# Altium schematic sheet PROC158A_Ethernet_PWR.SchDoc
size 431 x 279 mm; Date: Not shown in title block; ApprovedBy: Not shown in title block; CheckedBy: Not shown in title block; Author: Not shown in title block; CompanyName: Not shown in title block; Engineer: Not shown in title block; Organization: Not shown in title block; Address1: Not shown in title block; Address2: Not shown in title block; Address3: Not shown in title block; Address4: Not shown in title block; DocumentNumber: 11; Revision: Use project parameter SCH_Rev; SheetNumber: 11; SheetTotal: 24; PageSetup: Record=PageOptions¦CenterHorizontal=True¦CenterVertical=True¦PrintScale=1.00¦XCorrection=1.00¦YCorrection=1.00¦PrintKind=0¦BorderSize=5000000¦LeftOffset=0¦BottomOffset=0¦Orientation=2¦PaperLength=1000¦PaperWidth=1000¦Scale=100¦PaperSource=15¦PrintQuality=600¦MediaType=1¦DitherType=10¦PaperKind=Letter¦PrintScaleMode=1
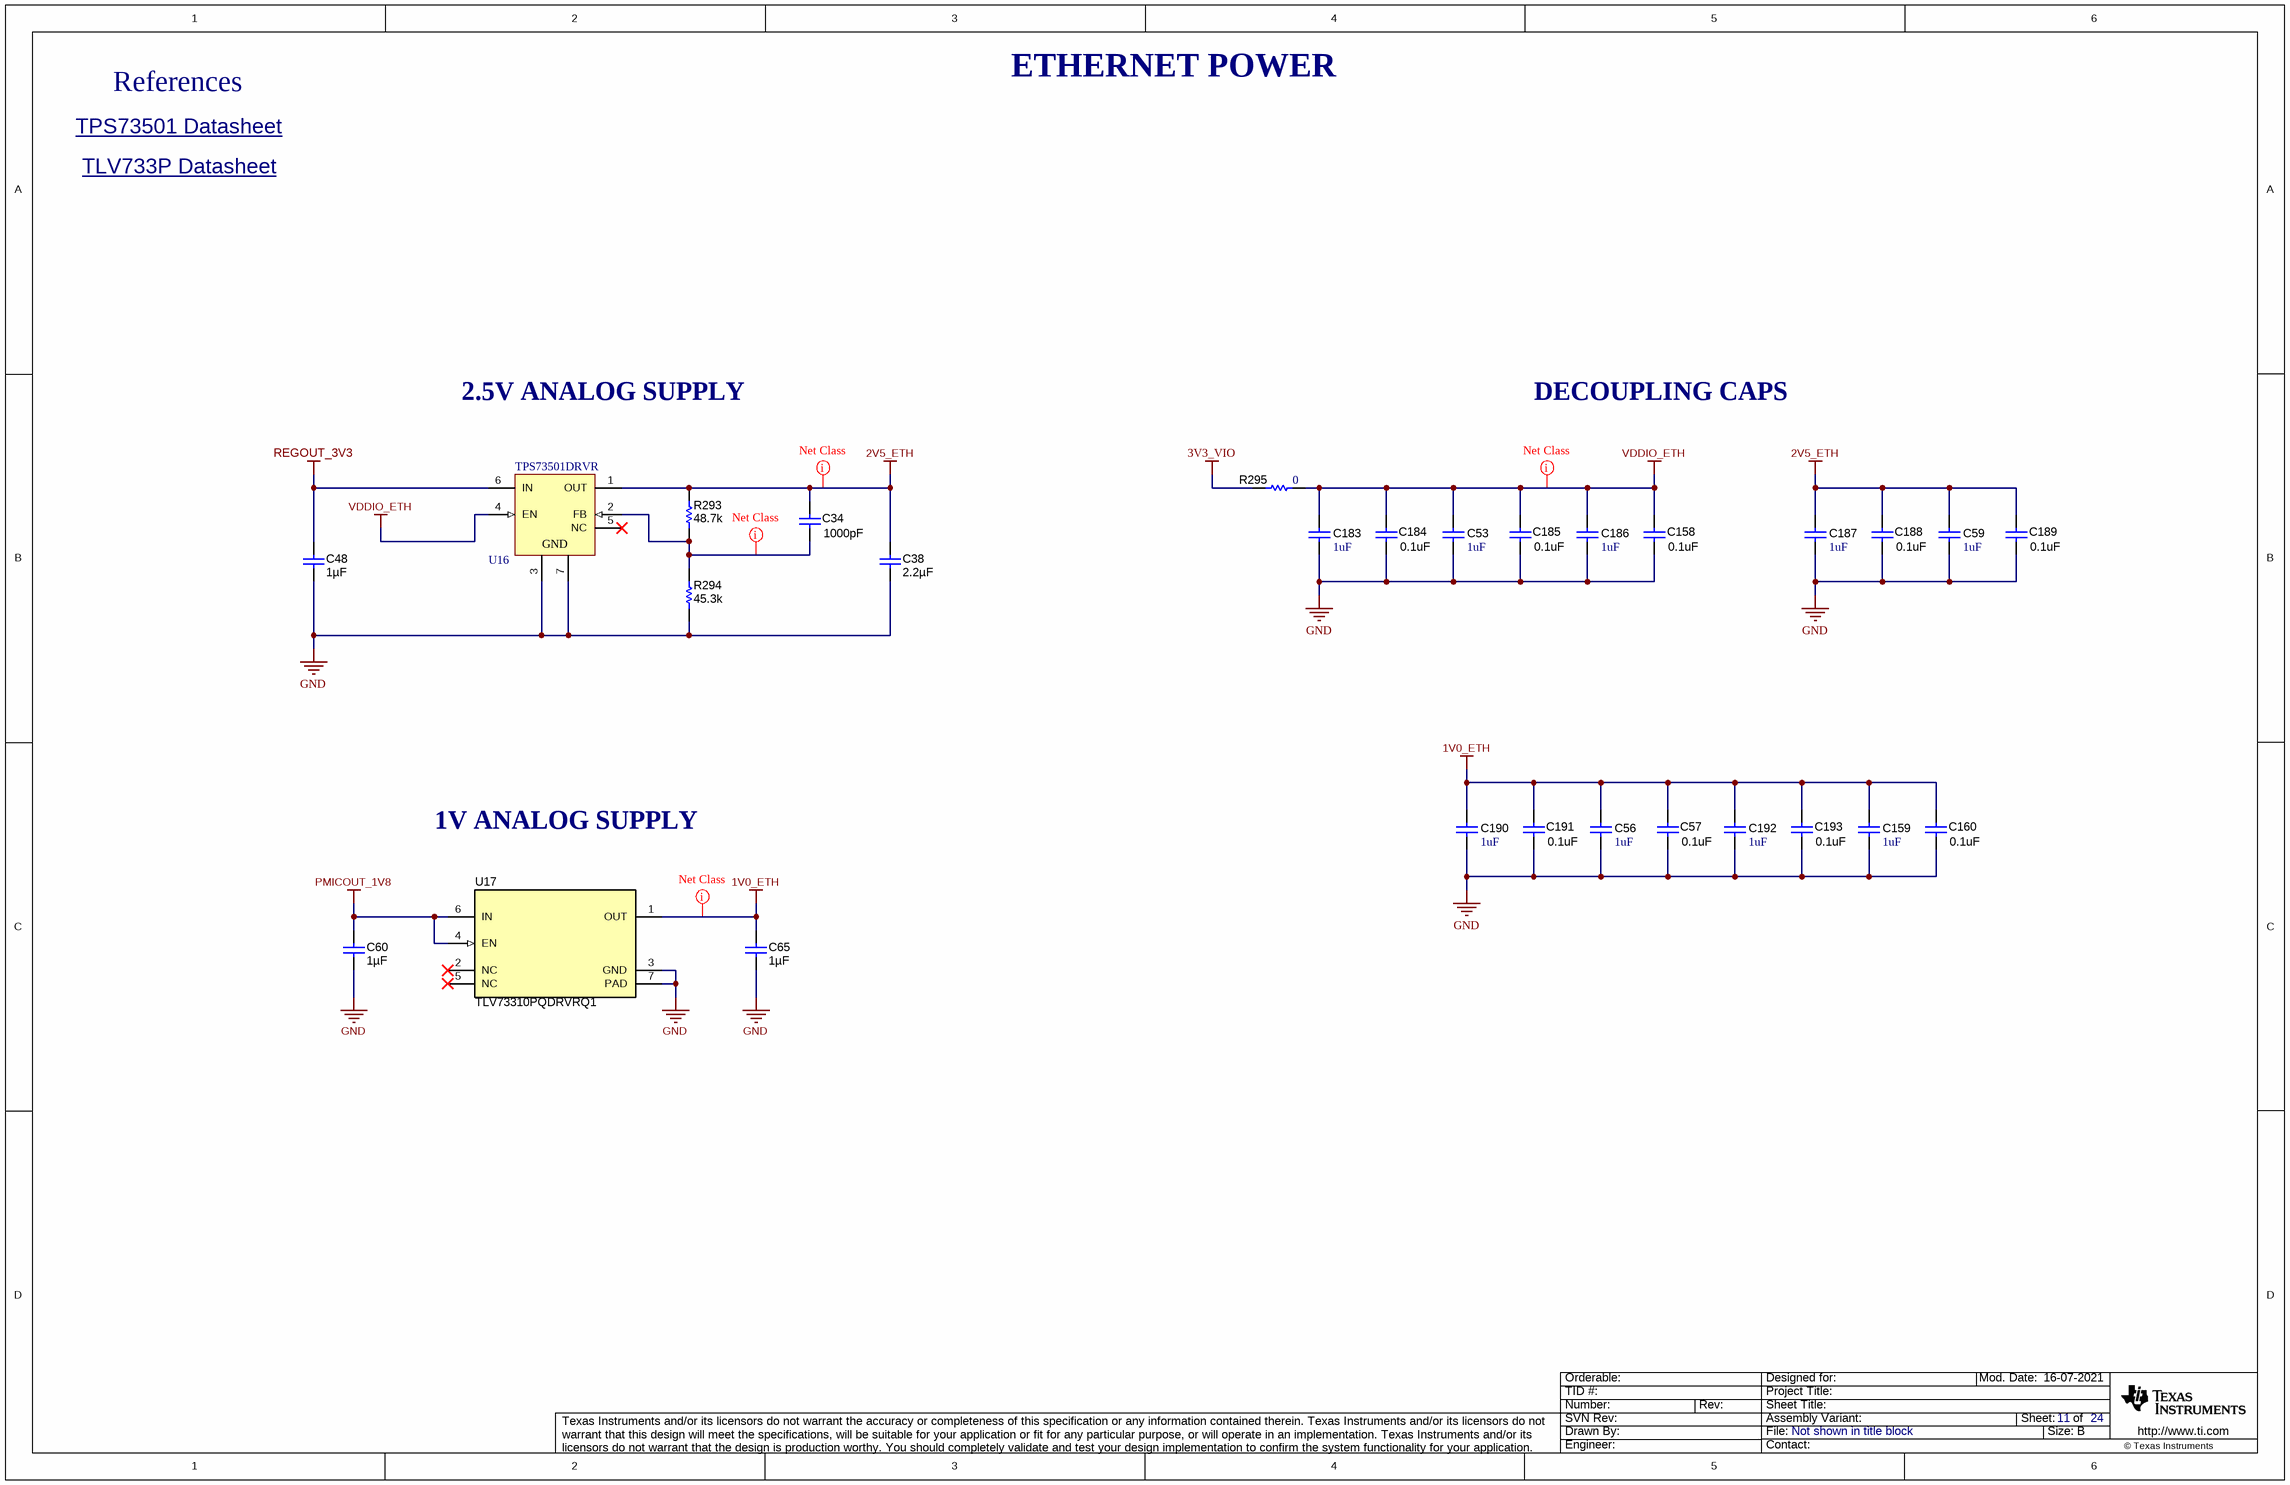
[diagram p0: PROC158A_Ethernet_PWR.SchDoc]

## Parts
C34  ValueDisplayed: 1000pF  [0402L]  (hidden comment: GCM155R71H102KA37D)
C38  Cap_F: 2.2µF  [0805L]  (hidden comment: CGA4J3X7R1H225K125AB)
C48  Cap_F: 1µF  [0603L]  (hidden comment: GCM188R71C105KA64D)
C53  ValueDisplayed: 1uF  [0603L]  (hidden comment: GCM188R71C105KA64D)
C56  ValueDisplayed: 1uF  [0603L]  (hidden comment: GCM188R71C105KA64D)
C57  ValueDisplayed: 0.1uF  [0402L]  (hidden comment: GCM155R71A104KA55D)
C59  ValueDisplayed: 1uF  [0603L]  (hidden comment: GCM188R71C105KA64D)
C60  Cap_F: 1µF  [0603L]  (hidden comment: GCM188R71C105KA64D)
C65  Cap_F: 1µF  [0603L]  (hidden comment: GCM188R71C105KA64D)
C158  ValueDisplayed: 0.1uF  [0402L]  (hidden comment: GCM155R71A104KA55D)
C159  ValueDisplayed: 1uF  [0603L]  (hidden comment: GCM188R71C105KA64D)
C160  ValueDisplayed: 0.1uF  [0402L]  (hidden comment: GCM155R71A104KA55D)
C183  ValueDisplayed: 1uF  [0603L]  (hidden comment: GCM188R71C105KA64D)
C184  ValueDisplayed: 0.1uF  [0402L]  (hidden comment: GCM155R71A104KA55D)
C185  ValueDisplayed: 0.1uF  [0402L]  (hidden comment: GCM155R71A104KA55D)
C186  ValueDisplayed: 1uF  [0603L]  (hidden comment: GCM188R71C105KA64D)
C187  ValueDisplayed: 1uF  [0603L]  (hidden comment: GCM188R71C105KA64D)
C188  ValueDisplayed: 0.1uF  [0402L]  (hidden comment: GCM155R71A104KA55D)
C189  ValueDisplayed: 0.1uF  [0402L]  (hidden comment: GCM155R71A104KA55D)
C190  ValueDisplayed: 1uF  [0603L]  (hidden comment: GCM188R71C105KA64D)
C191  ValueDisplayed: 0.1uF  [0402L]  (hidden comment: GCM155R71A104KA55D)
C192  ValueDisplayed: 1uF  [0603L]  (hidden comment: GCM188R71C105KA64D)
C193  ValueDisplayed: 0.1uF  [0402L]  (hidden comment: GCM155R71A104KA55D)
R293  ValueDisplayed: 48.7k  [0603L]  (hidden comment: CRCW060348K7FKEA)
R294  ValueDisplayed: 45.3k  [0603L]  (hidden comment: CRCW060345K3FKEA)
R295  ValueDisplayed: 0  [0402L]  (hidden comment: ERJ-2GE0R00X)
U16  TPS73501DRVR  [DRV0006A]
U17  TLV73310PQDRVRQ1  [DRV0006A]

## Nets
1V0_ETH: C56.1 C57.1 C65.1 C159.1 C160.1 C190.1 C191.1 C192.1 C193.1 U17.1(OUT)
2V5_ETH: C34.1 C38.1 C59.1 C187.1 C188.1 C189.1 R293.2 U16.1(OUT)
3V3_VIO: R295.2
GND: C38.2 C48.2 C53.2 C56.2 C57.2 C59.2 C60.2 C65.2 C158.2 C159.2 C160.2 C183.2 C184.2 C185.2 C186.2 C187.2 C188.2 C189.2 C190.2 C191.2 C192.2 C193.2 R294.1 U16.3(GND) U16.7(GND) U17.3(GND) U17.7(PAD)
PMICOUT_1V8: C60.1 U17.4(EN) U17.6(IN)
REGOUT_3V3: C48.1 U16.6(IN)
VDDIO_ETH: C53.1 C158.1 C183.1 C184.1 C185.1 C186.1 R295.1 U16.4(EN)
NetC34_2: C34.2 R293.1 R294.2 U16.2(FB)

Not connected (* = marked no-connect by the designer): U16 5(NC)*; U17 2(NC)* 5(NC)*

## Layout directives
net class PWR: 1V0_ETH, 2V5_ETH, NetC34_2, VDDIO_ETH

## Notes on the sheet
- References
- ETHERNET POWER
- TPS73501 Datasheet <http://www.ti.com/lit/ds/symlink/tps735.pdf>
- TLV733P Datasheet <http://www.ti.com/lit/ds/symlink/tlv733p.pdf>
- 2.5V ANALOG SUPPLY
- DECOUPLING CAPS
- 1V ANALOG SUPPLY

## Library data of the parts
C34 = CMP-0006354-2: CAP, CERM, 1000 pF, 50 V, +/- 10%, X7R, AEC-Q200 Grade 1, 0402; Manufacturer: MuRata; TaMin_C: -55°C; Polarized: N; SizeAreaWB_mm2: 3; Value1: Unknown; U/M: EA; Value: 1000pF; TaMax_C: 125°C; SizeZ_mm: 0.6; SizeX_mm: 1; SizeY_mm: 0.5; Cap_Case: 0402; Value2: 50V; AEC Qualified: Y; Cap_F: 1nF; AEC Category: Q200
C38 = CMP-0007977-2: CAP, CERM, 2.2 uF, 50 V, +/- 10%, X7R, AEC-Q200 Grade 1, 0805; Manufacturer: TDK; TaMin_C: -55°C; ESR_ohm: 3.288m; Polarized: N; SizeAreaWB_mm2: 6.75; Value1: 0.003288 ohm; U/M: EA; Value: 2.2uF; TaMax_C: 125°C; SizeZ_mm: 1.45; SizeX_mm: 2; SizeY_mm: 1.25; Cap_Case: 0805; Value2: 50V; SizeArea_mm2: 2.5; AEC Qualified: Y; IRMS_A: 3.60029A; AEC Grade: 1; AEC Category: Q200
C48 C60 C65 = CMP-0007136-5: CAP, CERM, 1 uF, 16 V, +/- 10%, X7R, AEC-Q200 Grade 1, 0603; Manufacturer: MuRata; TaMin_C: -55°C; Polarized: N; SizeAreaWB_mm2: 4.68; Value1: Unknown; U/M: EA; Value: 1uF; TaMax_C: 125°C; SizeZ_mm: 1; SizeX_mm: 1.6; SizeY_mm: 0.8; Cap_Case: 0603; Value2: 16V; SizeArea_mm2: 1.28; AEC Qualified: Y; AEC Category: Q200
C53 C56 C59 C159 C183 C186 C187 C190 C192 = CMP-0007136-5: CAP, CERM, 1 uF, 16 V, +/- 10%, X7R, AEC-Q200 Grade 1, 0603; Manufacturer: MuRata; TaMin_C: -55°C; Polarized: N; SizeAreaWB_mm2: 4.68; Value1: Unknown; U/M: EA; Value: 1uF; TaMax_C: 125°C; SizeZ_mm: 1; SizeX_mm: 1.6; SizeY_mm: 0.8; Cap_Case: 0603; Value2: 16V; SizeArea_mm2: 1.28; CompType: Capacitor; AEC Qualified: Y; Cap_F: 1µF; AEC Category: Q200
C57 C158 C160 C184 C185 C188 C189 C191 C193 = CMP-0006350-2: CAP, CERM, 0.1 uF, 10 V, +/- 10%, X7R, AEC-Q200 Grade 1, 0402; Manufacturer: MuRata; TaMin_C: -55°C; Polarized: N; SizeAreaWB_mm2: 3; Value1: Unknown; U/M: EA; Value: 0.1uF; TaMax_C: 125°C; SizeZ_mm: 0.6; SizeX_mm: 1; SizeY_mm: 0.5; Cap_Case: 0402; Value2: 10V; AEC Qualified: Y; Cap_F: 100nF; AEC Category: Q200
R293 = CMP-0022443-4: RES, 48.7 k, 1%, 0.1 W, AEC-Q200 Grade 0, 0603; Manufacturer: Vishay-Dale; Power_W: 100mW; TempCo: 100 ppm/C; Value_Code: 48k7; Value: 48.7k; EIA_Code: E96; SizeX_mm: 1.6; SizeY_mm: 0.8; SizeZ_mm: 1; Value2: 0.1W; SizeArea_mm2: 1.28; AEC Qualified: Y; VDC_V: 75V; AEC Category: Q200; AEC Grade: 0
R294 = CMP-0022430-4: RES, 45.3 k, 1%, 0.1 W, AEC-Q200 Grade 0, 0603; Manufacturer: Vishay-Dale; Power_W: 100mW; TempCo: 100 ppm/C; Value_Code: 45k3; Value: 45.3k; EIA_Code: E96; SizeX_mm: 1.6; SizeY_mm: 0.8; SizeZ_mm: 1; Value2: 0.1W; SizeArea_mm2: 1.28; AEC Qualified: Y; VDC_V: 75V; AEC Category: Q200; AEC Grade: 0
R295 = CMP-0026992-3: RES, 0, 5%, 0.1 W, AEC-Q200 Grade 0, 0402; Manufacturer: Panasonic; Power_W: 100mW; TempCo: 600 ppm/C; Value_Code: 0000; Value: 0; EIA_Code: E24; SizeX_mm: 1; SizeY_mm: 0.5; SizeZ_mm: 0.6; Value2: 0.1W; CompType: Resistor; AEC Qualified: Y; VDC_V: 50V; AEC Category: Q200; SizeAreaWB_mm2: 3; INSTALLATION: DNP
U16 = CMP-0036314-5: Single Output High PSRR LDO, 500 mA, Adjustable 1.25 to 6 V Output, 2.7 to 6.5 V Input, with Low IQ, 6-pin SON (DRV), -40 to 125 degC, Green (RoHS & no Sb/Br); Manufacturer: Texas Instruments; SubFamily: Single Channel LDO; Vin(Max)(V): 6.5; Vin(Min)(V): 2.7; Iout(Max)(A): 0.5; Iq(Typ)(mA): 0.04; Vdo(Typ)(mV): 280; Vout Adj(Max)(V): 6; Vout Adj(Min)(V): 1.25; Accuracy(%): 2; CompType: IC; SizeAreaWB_mm2: 9; SizeArea_mm2: 4; SizeZ_mm: 0.8
U17 = CMP-0078869-1: Capacitor-Free, 300-mA, Low-Dropout Regulator for Automotive, DRV0006A (WSON-6); Alternate Manufacturer: Texas Instruments; SizeAreaWB_mm2: 9; SizeZ_mm: 0.8; SizeX_mm: 2; SizeArea_mm2: 4; CompType: IC; AEC Qualified: Y; AEC Category: Q200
